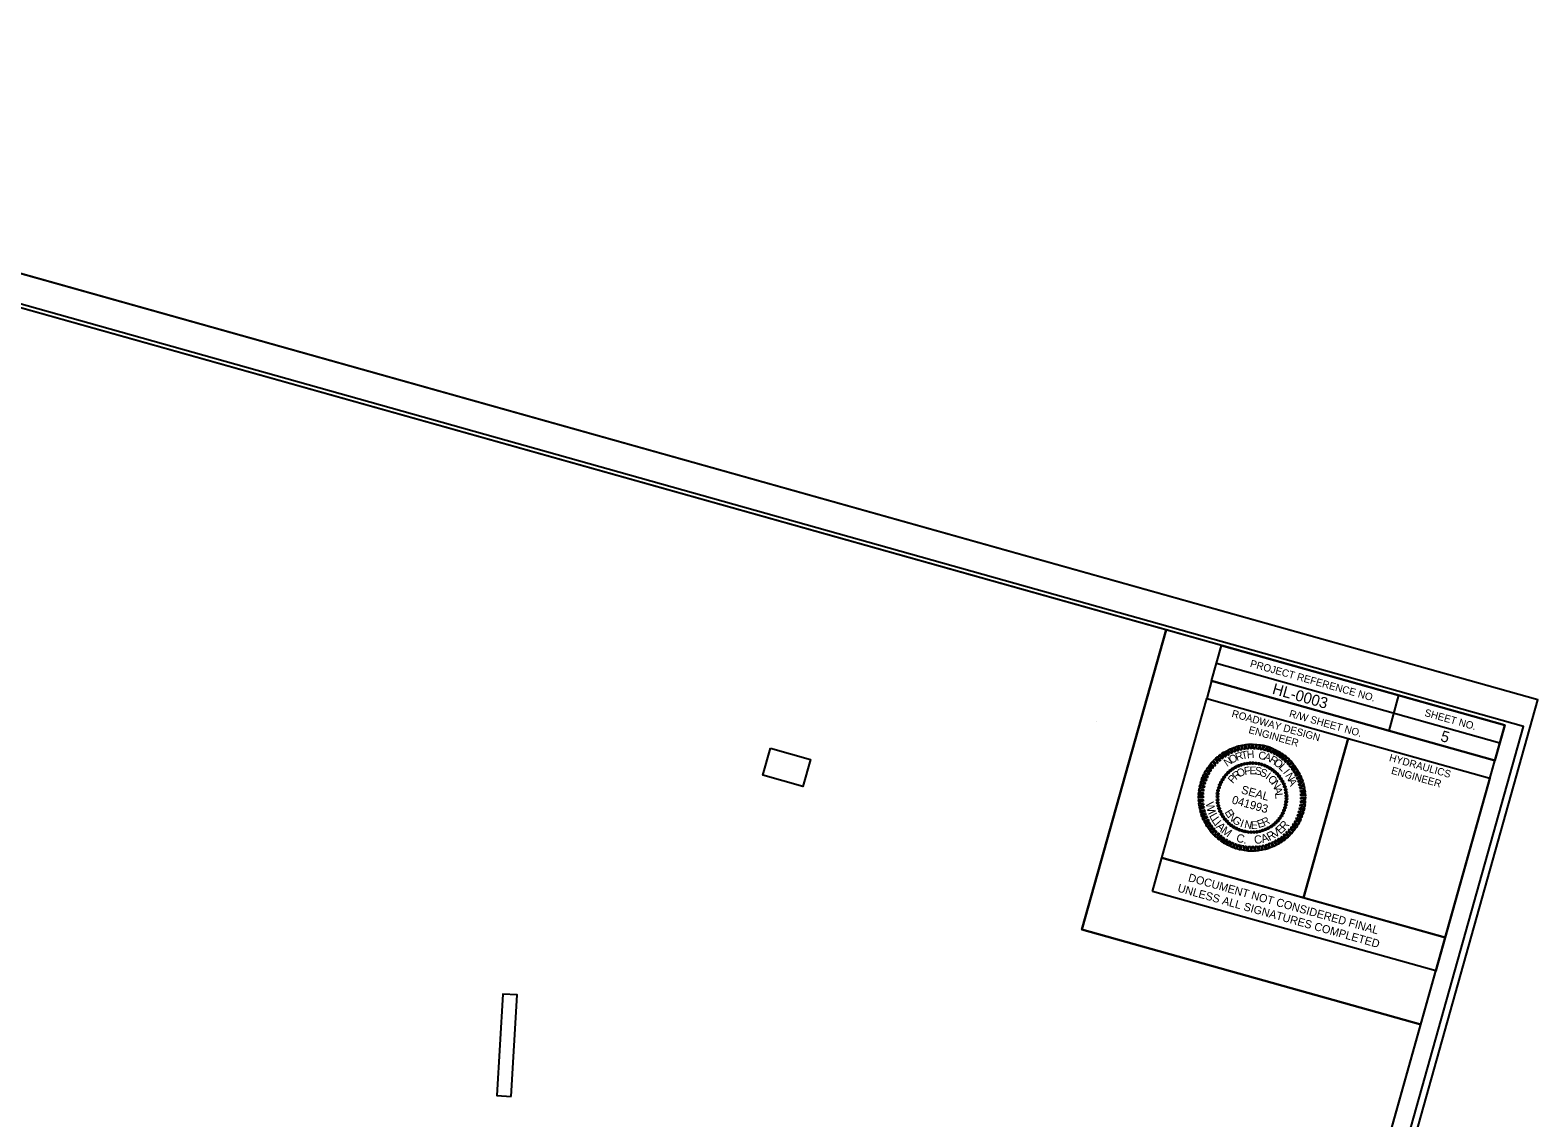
# Model space of a CAD drawing. Extents: x 928111 to 937215, y 684320 to 686530.
# Drawn here: x 929882 to 930907, y 685714 to 686453 of the extents above; entities that cross this region are included whole.
import ezdxf

# ---------------------------------------------------------------- set-up
doc = ezdxf.new("R2010")
doc.units = 0
for name, color, linetype in [('Default', 7, 'Continuous'), ('Prop DSN Text', 7, 'Continuous'), ('Sheet Cutting Line CELL', 7, 'Continuous'), ('Sheet Data Field CELL', 7, 'Continuous'), ('Sheet North Arrow Point CELL', 7, 'Continuous'), ('Sheet Plan CELL', 7, 'Continuous'), ('Sheet Plan Layout CELL', 7, 'Continuous'), ('Sheet Plot Border Inside CELL', 7, 'Continuous'), ('Sheet Plot Border Outside CELL', 7, 'Continuous')]:
    doc.layers.add(name, color=color, linetype=linetype)

msp = doc.modelspace()

# ---------------------------------------------------------------- linework, layer by layer
at = {"layer": 'Default'}
for p, q in [((930696.8, 685948.3), (930696.8, 685948.3)), ((930698.4, 685949.6), (930698.4, 685949.6)), ((930700.1, 685950.9), (930700.1, 685950.9)), ((930701.8, 685951.9), (930701.8, 685951.9)), ((930703.7, 685952.8), (930703.7, 685952.8)), ((930705.6, 685953.5), (930705.6, 685953.5)), ((930707.6, 685954.1), (930707.6, 685954.1)), ((930709.6, 685954.5), (930709.6, 685954.5)), ((930711.6, 685954.7), (930711.6, 685954.7)), ((930713.6, 685954.7), (930713.6, 685954.7)), ((930715.7, 685954.5), (930715.7, 685954.5)), ((930717.7, 685954.2), (930717.7, 685954.2)), ((930719.7, 685953.7), (930719.7, 685953.7)), ((930721.7, 685953), (930721.7, 685953)), ((930723.5, 685952.2), (930723.5, 685952.2)), ((930725.3, 685951.2), (930725.3, 685951.2)), ((930727, 685950.1), (930727, 685950.1)), ((930728.6, 685948.7), (930728.6, 685948.7)), ((930730.1, 685947.3), (930730.1, 685947.3)), ((930690.4, 685938), (930690.4, 685938)), ((930691.1, 685939.9), (930691.1, 685939.9)), ((930692, 685941.7), (930692, 685941.7)), ((930692.9, 685943.5), (930692.9, 685943.5)), ((930694.1, 685945.2), (930694.1, 685945.2)), ((930695.4, 685946.8), (930695.4, 685946.8)), ((930731.4, 685945.8), (930731.4, 685945.8)), ((930732.7, 685944.1), (930732.7, 685944.1)), ((930733.7, 685942.4), (930733.7, 685942.4)), ((930734.6, 685940.5), (930734.6, 685940.5)), ((930735.3, 685938.6), (930735.3, 685938.6)), ((930689.5, 685931.8), (930689.5, 685931.8)), ((930689.5, 685929.8), (930689.5, 685929.8)), ((930689.6, 685933.9), (930689.6, 685933.9)), ((930689.7, 685927.8), (930689.7, 685927.8)), ((930689.9, 685936), (930689.9, 685936)), ((930713, 685931.2), (930713, 685931.2)), ((930735.9, 685936.6), (930735.9, 685936.6)), ((930736.3, 685934.6), (930736.3, 685934.6)), ((930736.3, 685928.4), (930736.3, 685928.4)), ((930736.5, 685932.6), (930736.5, 685932.6)), ((930736.5, 685930.5), (930736.5, 685930.5)), ((930690.1, 685925.8), (930690.1, 685925.8)), ((930690.6, 685923.8), (930690.6, 685923.8)), ((930691.3, 685921.9), (930691.3, 685921.9)), ((930692.3, 685920), (930692.3, 685920)), ((930693.3, 685918.3), (930693.3, 685918.3)), ((930694.5, 685916.6), (930694.5, 685916.6)), ((930731.9, 685917.1), (930731.9, 685917.1)), ((930733, 685918.8), (930733, 685918.8)), ((930734, 685920.6), (930734, 685920.6)), ((930734.8, 685922.5), (930734.8, 685922.5)), ((930735.5, 685924.4), (930735.5, 685924.4)), ((930736, 685926.4), (930736, 685926.4)), ((930695.8, 685915), (930695.8, 685915)), ((930697.3, 685913.6), (930697.3, 685913.6)), ((930698.9, 685912.3), (930698.9, 685912.3)), ((930700.6, 685911.1), (930700.6, 685911.1)), ((930702.4, 685910.2), (930702.4, 685910.2)), ((930704.3, 685909.3), (930704.3, 685909.3)), ((930706.2, 685908.6), (930706.2, 685908.6)), ((930708.2, 685908.1), (930708.2, 685908.1)), ((930710.2, 685907.9), (930710.2, 685907.9)), ((930712.3, 685907.7), (930712.3, 685907.7)), ((930714.4, 685907.7), (930714.4, 685907.7)), ((930716.4, 685907.9), (930716.4, 685907.9)), ((930718.4, 685908.3), (930718.4, 685908.3)), ((930720.4, 685908.8), (930720.4, 685908.8)), ((930722.3, 685909.5), (930722.3, 685909.5)), ((930724.1, 685910.5), (930724.1, 685910.5)), ((930725.9, 685911.5), (930725.9, 685911.5)), ((930727.6, 685912.7), (930727.6, 685912.7)), ((930729.1, 685914), (930729.1, 685914)), ((930730.5, 685915.5), (930730.5, 685915.5))]:
    msp.add_line(p, q, dxfattribs=at)
for points in [[(930709.3, 685964.4), (930708.9, 685967.3), (930710.4, 685967.5), (930710.5, 685964.3)], [(930711.7, 685964.5), (930711.4, 685967.5), (930712.9, 685967.5), (930712.7, 685964.5)], [(930714, 685964.4), (930713.9, 685967.5), (930715.5, 685967.4), (930715, 685964.4)], [(930688.9, 685954.3), (930686.6, 685956.1), (930687.7, 685957.3), (930689.7, 685955)], [(930690.5, 685955.9), (930688.4, 685958), (930689.6, 685959), (930691.5, 685956.5)], [(930692.4, 685957.3), (930690.4, 685959.5), (930691.6, 685960.6), (930693.2, 685958)], [(930694.2, 685958.7), (930692.4, 685961.1), (930693.7, 685962), (930695.1, 685959.3)], [(930696.3, 685959.9), (930694.5, 685962.4), (930695.9, 685963.1), (930697.2, 685960.4)], [(930698.2, 685961.1), (930696.8, 685963.6), (930698.2, 685964.4), (930699.2, 685961.5)], [(930700.4, 685962), (930699.1, 685964.7), (930700.6, 685965.3), (930701.4, 685962.3)], [(930702.5, 685962.9), (930701.5, 685965.6), (930702.9, 685966.2), (930703.6, 685963.1)], [(930704.8, 685963.4), (930703.8, 685966.3), (930705.4, 685966.7), (930705.8, 685963.7)], [(930707, 685964), (930706.3, 685966.9), (930707.9, 685967.1), (930708.1, 685964.1)], [(930716.3, 685964.3), (930716.4, 685967.4), (930718, 685967.1), (930717.5, 685964.1)], [(930718.6, 685964), (930718.9, 685967), (930720.5, 685966.8), (930719.7, 685963.8)], [(930720.9, 685963.6), (930721.5, 685966.6), (930723, 685966.1), (930722, 685963.2)], [(930723.1, 685962.9), (930723.9, 685965.9), (930725.4, 685965.4), (930724.1, 685962.6)], [(930725.3, 685962.1), (930726.3, 685965), (930727.7, 685964.3), (930726.3, 685961.7)], [(930727.3, 685961.2), (930728.6, 685964), (930730, 685963.3), (930728.4, 685960.7)], [(930729.5, 685960), (930730.8, 685962.8), (930732.2, 685962.1), (930730.4, 685959.5)], [(930731.5, 685958.8), (930733, 685961.4), (930734.2, 685960.6), (930732.4, 685958.3)], [(930733.3, 685957.5), (930735.1, 685960), (930736.3, 685959.1), (930734.3, 685956.9)], [(930735.1, 685956), (930737, 685958.4), (930738.2, 685957.4), (930736, 685955.3)], [(930682.4, 685944.5), (930679.6, 685945.6), (930680.2, 685947.1), (930683, 685945.5)], [(930683.5, 685946.7), (930680.8, 685947.9), (930681.5, 685949.3), (930684.1, 685947.6)], [(930684.6, 685948.7), (930682, 685950.1), (930682.8, 685951.5), (930685.3, 685949.6)], [(930685.9, 685950.7), (930683.4, 685952.3), (930684.3, 685953.5), (930686.7, 685951.5)], [(930687.4, 685952.4), (930684.9, 685954.3), (930686, 685955.5), (930688.1, 685953.3)], [(930736.9, 685954.4), (930738.8, 685956.6), (930740, 685955.5), (930737.6, 685953.6)], [(930738.3, 685952.7), (930740.6, 685954.9), (930741.5, 685953.6), (930739.1, 685951.9)], [(930739.8, 685950.8), (930742.1, 685952.8), (930743, 685951.5), (930740.4, 685950)], [(930741.1, 685948.9), (930743.6, 685950.8), (930744.4, 685949.4), (930741.8, 685948)], [(930742.3, 685946.9), (930744.8, 685948.5), (930745.6, 685947.1), (930742.7, 685946)], [(930680, 685935.7), (930676.9, 685935.9), (930677.2, 685937.4), (930680.1, 685936.8)], [(930680.3, 685937.9), (930677.3, 685938.4), (930677.7, 685939.9), (930680.6, 685939)], [(930680.9, 685940.2), (930678, 685940.9), (930678.4, 685942.4), (930681.2, 685941.3)], [(930681.6, 685942.4), (930678.7, 685943.3), (930679.2, 685944.8), (930682, 685943.5)], [(930743.4, 685944.8), (930746, 685946.3), (930746.6, 685944.8), (930743.8, 685943.8)], [(930744.3, 685942.7), (930747, 685944), (930747.5, 685942.4), (930744.6, 685941.7)], [(930744.9, 685940.5), (930747.8, 685941.6), (930748.3, 685940), (930745.3, 685939.4)], [(930745.5, 685938.2), (930748.5, 685939.1), (930748.7, 685937.5), (930745.8, 685937.2)], [(930679.7, 685931.1), (930676.6, 685930.8), (930676.7, 685932.4), (930679.7, 685932.1)], [(930679.8, 685933.4), (930676.7, 685933.3), (930676.9, 685934.9), (930679.8, 685934.4)], [(930679.9, 685928.7), (930676.8, 685928.3), (930676.7, 685929.8), (930679.7, 685929.8)], [(930680.1, 685926.4), (930677, 685925.7), (930676.8, 685927.4), (930679.9, 685927.5)], [(930745.9, 685926.7), (930749.1, 685926.5), (930748.8, 685924.9), (930745.8, 685925.6)], [(930745.9, 685936), (930748.9, 685936.6), (930749.1, 685935), (930746.1, 685934.9)], [(930746.1, 685933.7), (930749.2, 685934.1), (930749.3, 685932.5), (930746.3, 685932.6)], [(930746.1, 685929), (930749.2, 685929), (930749.1, 685927.4), (930746.1, 685927.9)], [(930746.2, 685931.3), (930749.4, 685931.5), (930749.2, 685930), (930746.3, 685930.3)], [(930680.4, 685924.2), (930677.5, 685923.3), (930677.3, 685924.9), (930680.1, 685925.2)], [(930681, 685921.8), (930678.2, 685920.8), (930677.7, 685922.4), (930680.7, 685922.9)], [(930681.7, 685919.7), (930679, 685918.4), (930678.5, 685919.9), (930681.4, 685920.7)], [(930682.6, 685917.5), (930679.9, 685916.1), (930679.3, 685917.6), (930682.2, 685918.6)], [(930683.7, 685915.5), (930681.1, 685913.9), (930680.4, 685915.3), (930683.2, 685916.4)], [(930743.5, 685917.8), (930746.3, 685916.8), (930745.7, 685915.3), (930743, 685916.8)], [(930744.3, 685919.9), (930747.2, 685919), (930746.7, 685917.6), (930743.9, 685918.9)], [(930745, 685922.2), (930748, 685921.5), (930747.6, 685920), (930744.7, 685921.1)], [(930745.6, 685924.4), (930748.6, 685924), (930748.3, 685922.4), (930745.4, 685923.3)], [(930684.9, 685913.4), (930682.3, 685911.6), (930681.6, 685913), (930684.2, 685914.3)], [(930686.2, 685911.5), (930683.8, 685909.5), (930682.9, 685910.8), (930685.5, 685912.4)], [(930687.7, 685909.7), (930685.3, 685907.5), (930684.4, 685908.8), (930686.8, 685910.5)], [(930689.1, 685908), (930687.1, 685905.7), (930686, 685906.9), (930688.4, 685908.7)], [(930690.9, 685906.3), (930689, 685904), (930687.8, 685905), (930690, 685907.1)], [(930735.4, 685906.5), (930737.6, 685904.4), (930736.3, 685903.4), (930734.5, 685905.9)], [(930737.1, 685908.1), (930739.3, 685906.3), (930738.3, 685905), (930736.3, 685907.4)], [(930738.6, 685909.9), (930741.1, 685908.1), (930740, 685906.9), (930737.8, 685909.1)], [(930740, 685911.7), (930742.6, 685910.1), (930741.6, 685908.8), (930739.3, 685910.8)], [(930741.3, 685913.6), (930743.9, 685912.3), (930743.2, 685910.9), (930740.7, 685912.8)], [(930742.5, 685915.6), (930745.2, 685914.5), (930744.4, 685913), (930741.9, 685914.8)], [(930692.6, 685904.9), (930690.8, 685902.4), (930689.7, 685903.2), (930691.7, 685905.5)], [(930694.4, 685903.5), (930693, 685900.9), (930691.7, 685901.8), (930693.6, 685904.1)], [(930696.4, 685902.3), (930695.2, 685899.5), (930693.7, 685900.3), (930695.6, 685902.8)], [(930698.6, 685901.2), (930697.4, 685898.4), (930696, 685899.1), (930697.6, 685901.6)], [(930700.7, 685900.2), (930699.7, 685897.3), (930698.3, 685898), (930699.6, 685900.7)], [(930702.9, 685899.4), (930702.1, 685896.5), (930700.6, 685897), (930701.8, 685899.8)], [(930705, 685898.8), (930704.4, 685895.8), (930703, 685896.3), (930704, 685899.1)], [(930707.4, 685898.4), (930707.1, 685895.4), (930705.5, 685895.6), (930706.2, 685898.6)], [(930709.6, 685898), (930709.5, 685895), (930708, 685895.2), (930708.5, 685898.2)], [(930711.9, 685897.9), (930712.1, 685894.8), (930710.4, 685894.9), (930710.9, 685898)], [(930714.2, 685897.9), (930714.5, 685894.9), (930713, 685894.9), (930713.2, 685897.9)], [(930716.7, 685898), (930717.1, 685895.1), (930715.6, 685894.9), (930715.5, 685898.1)], [(930718.9, 685898.4), (930719.6, 685895.5), (930718.1, 685895.2), (930717.8, 685898.3)], [(930721.2, 685898.9), (930722.1, 685896), (930720.5, 685895.7), (930720.1, 685898.6)], [(930723.5, 685899.5), (930724.5, 685896.7), (930723.1, 685896.2), (930722.3, 685899.2)], [(930725.6, 685900.4), (930726.9, 685897.7), (930725.4, 685897.1), (930724.5, 685900)], [(930727.8, 685901.3), (930729.2, 685898.7), (930727.8, 685898), (930726.7, 685900.9)], [(930729.7, 685902.4), (930731.5, 685899.9), (930730, 685899.2), (930728.8, 685901.9)], [(930731.7, 685903.7), (930733.6, 685901.3), (930732.3, 685900.4), (930730.9, 685903.1)], [(930733.6, 685905), (930735.6, 685902.8), (930734.4, 685901.8), (930732.8, 685904.3)]]:
    msp.add_lwpolyline(points, close=True, dxfattribs=at)
for centre, major_axis in [((930695.4, 685946.8), (-0.504, 0.449)), ((930696.8, 685948.3), (-0.463, 0.491)), ((930698.4, 685949.6), (-0.418, 0.53)), ((930700.1, 685950.8), (-0.371, 0.564)), ((930701.8, 685951.9), (-0.32, 0.594)), ((930703.7, 685952.8), (-0.267, 0.62)), ((930705.6, 685953.5), (-0.212, 0.641)), ((930707.6, 685954.1), (-0.155, 0.657)), ((930709.6, 685954.4), (-0.098, 0.668)), ((930711.6, 685954.7), (-0.039, 0.674)), ((930713.7, 685954.7), (0.02, 0.675)), ((930715.7, 685954.5), (0.079, 0.67)), ((930717.7, 685954.2), (0.137, 0.661)), ((930719.7, 685953.7), (0.194, 0.647)), ((930721.7, 685953), (0.249, 0.627)), ((930723.5, 685952.2), (0.303, 0.603)), ((930725.3, 685951.2), (0.355, 0.574)), ((930727, 685950), (0.403, 0.541)), ((930728.6, 685948.7), (0.449, 0.504)), ((930730.1, 685947.3), (0.491, 0.463)), ((930689.9, 685935.9), (-0.661, 0.137)), ((930690.5, 685937.9), (-0.647, 0.194)), ((930691.1, 685939.9), (-0.627, 0.249)), ((930692, 685941.7), (-0.603, 0.303)), ((930693, 685943.5), (-0.574, 0.355)), ((930694.1, 685945.2), (-0.541, 0.403)), ((930731.4, 685945.8), (0.53, 0.418)), ((930732.6, 685944.1), (0.564, 0.371)), ((930733.7, 685942.3), (0.594, 0.32)), ((930734.6, 685940.5), (0.62, 0.267)), ((930735.3, 685938.6), (0.641, 0.212)), ((930735.9, 685936.6), (0.657, 0.155)), ((930689.5, 685931.9), (-0.675, 0.02)), ((930689.5, 685929.8), (-0.674, -0.039)), ((930689.6, 685933.9), (-0.67, 0.079)), ((930689.7, 685927.8), (-0.668, -0.098)), ((930690.1, 685925.8), (-0.657, -0.155)), ((930736, 685926.4), (0.661, -0.137)), ((930736.2, 685934.6), (0.668, 0.098)), ((930736.3, 685928.4), (0.67, -0.079)), ((930736.4, 685932.5), (0.674, 0.039)), ((930736.5, 685930.5), (0.675, -0.02)), ((930690.7, 685923.8), (-0.641, -0.212)), ((930691.4, 685921.9), (-0.62, -0.267)), ((930692.3, 685920), (-0.594, -0.32)), ((930693.3, 685918.3), (-0.564, -0.371)), ((930694.5, 685916.6), (-0.53, -0.418)), ((930730.5, 685915.5), (0.504, -0.449)), ((930731.8, 685917.1), (0.541, -0.403)), ((930733, 685918.8), (0.574, -0.355)), ((930734, 685920.6), (0.603, -0.303)), ((930734.8, 685922.5), (0.627, -0.249)), ((930735.5, 685924.4), (0.647, -0.194)), ((930695.9, 685915.1), (-0.491, -0.463)), ((930697.3, 685913.6), (-0.449, -0.504)), ((930698.9, 685912.3), (-0.403, -0.541)), ((930700.6, 685911.2), (-0.355, -0.574)), ((930702.4, 685910.2), (-0.303, -0.603)), ((930704.3, 685909.3), (-0.249, -0.627)), ((930706.2, 685908.7), (-0.194, -0.647)), ((930708.2, 685908.2), (-0.137, -0.661)), ((930710.2, 685907.8), (-0.079, -0.67)), ((930712.3, 685907.7), (-0.02, -0.675)), ((930714.3, 685907.7), (0.039, -0.674)), ((930716.4, 685907.9), (0.098, -0.668)), ((930718.4, 685908.3), (0.155, -0.657)), ((930720.4, 685908.9), (0.212, -0.641)), ((930722.3, 685909.6), (0.267, -0.62)), ((930724.1, 685910.5), (0.32, -0.594)), ((930725.9, 685911.5), (0.371, -0.564)), ((930727.6, 685912.7), (0.418, -0.53)), ((930729.1, 685914.1), (0.463, -0.491))]:
    msp.add_ellipse(centre, major_axis=major_axis, ratio=0.999708, dxfattribs=at)
at = {"layer": 'Prop DSN Text'}
for points in [[(930385.5, 685964.9), (930412.9, 685957.2), (930407.7, 685938.7), (930380.3, 685946.4)], [(930209.2, 685728.1), (930213.4, 685797.1), (930203.6, 685797.7), (930199.5, 685728.7)]]:
    msp.add_lwpolyline(points, close=True, dxfattribs=at)
at = {"layer": 'Sheet Cutting Line CELL'}
msp.add_line((930907.4, 685997.6), (929286.6, 686452.8), dxfattribs=at)
at = {"layer": 'Sheet North Arrow Point CELL'}
msp.add_line((930607.1, 685982.8), (930607.1, 685982.8), dxfattribs=at)
at = {"layer": 'Sheet Plan CELL'}
for p, q in [((930688.9, 686022.6), (930881.5, 685968.5)), ((930685.5, 686010.5), (930682.2, 685998.5)), ((930685.5, 686010.5), (930878.1, 685956.4)), ((930812.7, 686000.8), (930806, 685976.7)), ((930645.4, 685867.5), (930651.8, 685890.2)), ((930651.8, 685890.2), (930844.3, 685836.1)), ((930838, 685813.5), (930645.4, 685867.5)), ((930844.3, 685836.1), (930838, 685813.4))]:
    msp.add_line(p, q, dxfattribs=at)
for points in [[(930884.9, 685980.5), (929440.8, 686386.2), (929156.9, 685375.3), (930601, 684969.7)], [(930597.4, 685841.6), (930827.7, 685776.9), (930885, 685980.5), (930654.6, 686045.2)], [(930692.3, 686034.6), (930884.9, 685980.5), (930878.1, 685956.4), (930685.5, 686010.5)], [(930682.2, 685998.5), (930778.5, 685971.4), (930748.1, 685863.1), (930651.8, 685890.2)], [(930778.5, 685971.4), (930874.8, 685944.4), (930844.3, 685836.1), (930748.1, 685863.1)]]:
    msp.add_lwpolyline(points, close=True, dxfattribs=at)
at = {"layer": 'Sheet Plan Layout CELL'}
msp.add_lwpolyline([(929440.8, 686386.2), (929156.9, 685375.3), (930601, 684969.7), (930827.7, 685776.9), (930597.4, 685841.6), (930654.6, 686045.2)], close=True, dxfattribs=at)
at = {"layer": 'Sheet Plot Border Inside CELL'}
msp.add_lwpolyline([(929008.4, 685414.4), (930612.3, 684963.9), (930897.6, 685979.6), (929293.7, 686430.1)], close=True, dxfattribs=at)
at = {"layer": 'Sheet Plot Border Outside CELL'}
msp.add_lwpolyline([(928990.5, 685398.6), (930611.3, 684943.4), (930907.4, 685997.6), (929286.6, 686452.8)], close=True, dxfattribs=at)

# ---------------------------------------------------------------- texts
at = {"layer": 'Default'}
for s, height, rotation, p in [('N', 5.29, 33.734, (930696, 685952)), ('O', 5.29, 26.5322, (930698.8, 685954.1)), ('R', 5.29, 19.331, (930702.7, 685956)), ('T', 5.29, 12.1303, (930706.3, 685957.1)), ('H', 5.29, 4.93, (930709.7, 685957.8)), ('C', 5.29, 350.5304, (930717, 685957.6)), ('A', 5.29, 343.3308, (930720.7, 685956.9)), ('R', 5.29, 328.9316, (930724.4, 685955.7)), ('O', 5.29, 321.7317, (930727.3, 685954.1)), ('R', 5.29, 38.3502, (930702.1, 685942.9)), ('O', 5.29, 28.9917, (930704.3, 685944.7)), ('F', 5.29, 10.2775, (930708.1, 685946.5)), ('E', 5.29, 0.9216, (930711.3, 685947)), ('S', 5.29, 351.5661, (930714.7, 685947.1)), ('S', 5.29, 342.2109, (930718, 685946.2)), ('I', 5.29, 323.5001, (930721.7, 685944.5)), ('L', 5.29, 314.5314, (930730.8, 685951.4)), ('I', 5.29, 307.3306, (930733.8, 685948.2)), ('N', 5.29, 300.1294, (930735.4, 685946.2)), ('P', 5.29, 47.7094, (930699.9, 685940.4)), ('SEAL', 5.62, 344.3105, (930705.2, 685934.2)), ('O', 5.29, 314.144, (930723.3, 685943.4)), ('N', 5.29, 304.7871, (930725.8, 685940.7)), ('A', 5.29, 286.0708, (930727.7, 685937.6)), ('A', 5.29, 292.9277, (930737.3, 685942.8)), ('W', 5.62, 282.6679, (930681.4, 685927.6)), ('041993', 5.62, 344.3105, (930698.9, 685927.3)), ('L', 5.29, 276.7114, (930728.6, 685934)), ('I', 5.62, 295.202, (930682.9, 685920.9)), ('L', 5.62, 299.0039, (930683.7, 685918.9)), ('L', 5.62, 305.2787, (930685.2, 685915.8)), ('E', 5.29, 302.5874, (930694.2, 685921.2)), ('N', 5.29, 311.9445, (930696.2, 685918)), ('G', 5.29, 321.3007, (930699.1, 685915)), ('I', 5.29, 340.0117, (930704.5, 685911.6)), ('E', 5.29, 17.4346, (930717.4, 685910.4)), ('R', 5.29, 26.7919, (930721.2, 685911.6)), ('I', 5.62, 311.5535, (930687, 685912.8)), ('A', 5.62, 315.3554, (930688.3, 685911.1)), ('M', 5.62, 324.1957, (930691.7, 685907.6)), ('C', 5.62, 345.9256, (930701.9, 685901.4)), ('N', 5.29, 349.3669, (930707.5, 685910.7)), ('E', 5.29, 358.7223, (930712.1, 685909.9)), ('A', 5.62, 19.324, (930720.2, 685900.2)), ('R', 5.62, 28.1643, (930724.8, 685901.7)), ('V', 5.62, 35.6446, (930728.6, 685903.5)), ('E', 5.62, 43.8976, (930732.4, 685906)), ('R', 5.62, 51.0069, (930735.4, 685908.6)), ('.', 5.62, 355.5077, (930707.1, 685900)), ('C', 5.62, 9.7418, (930714.9, 685899.5))]:
    msp.add_text(s, height=height, rotation=rotation, dxfattribs=at).set_placement(p)
at = {"layer": 'Sheet Data Field CELL'}
for s, p in [('HL-0003', (930726.3, 686001.9)), ('5', (930840.7, 685969.8))]:
    msp.add_text(s, height=7.5, rotation=344.3105, dxfattribs=at).set_placement(p)
at = {"layer": 'Sheet Plan CELL'}
for s, height, p in [('PROJECT REFERENCE NO.', 5, (930711.3, 686020.2)), ('ROADWAY DESIGN', 5, (930698.8, 685986.2)), ('R/W SHEET NO.', 5, (930737.9, 685986.2)), ('SHEET NO.', 5, (930829.9, 685986.8)), ('ENGINEER', 5, (930710.3, 685975.2)), ('HYDRAULICS', 5, (930805.9, 685956.2)), ('ENGINEER', 5, (930807.3, 685947.5)), ('DOCUMENT NOT CONSIDERED FINAL', 5.5, (930669.2, 685874.5)), ('UNLESS ALL SIGNATURES COMPLETED', 5.5, (930662, 685867.4))]:
    msp.add_text(s, height=height, rotation=344.3105, dxfattribs=at).set_placement(p)

doc.saveas('drawing.dxf')
